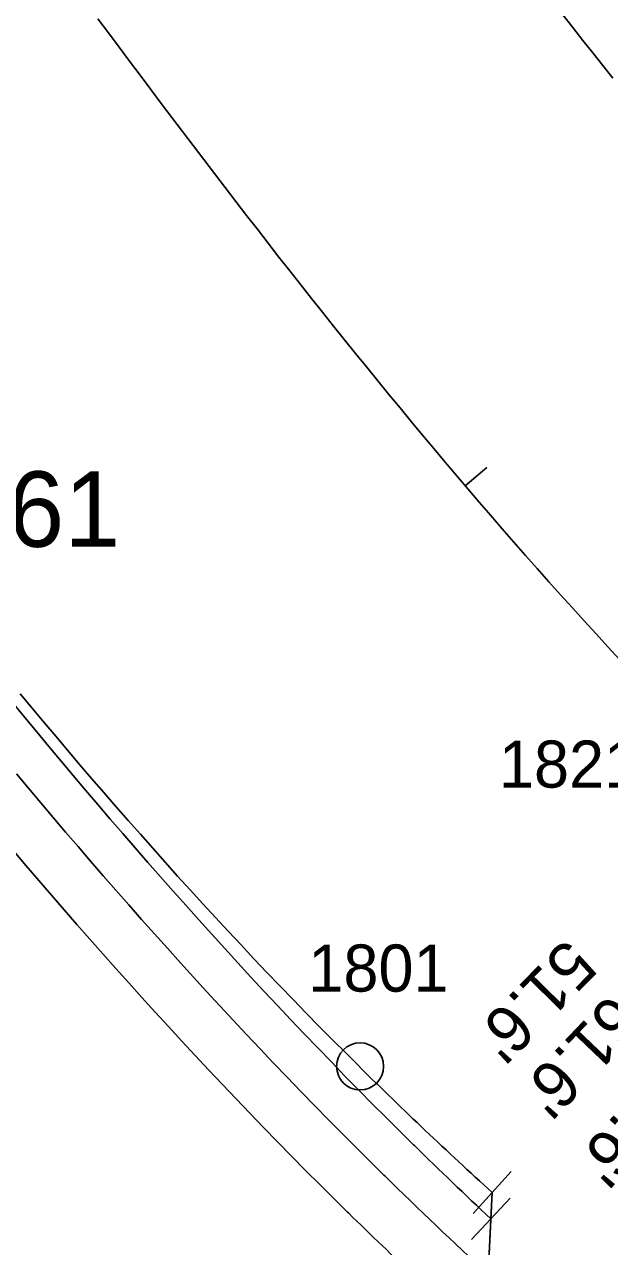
# Model space of a CAD drawing. Extents: x 7581380 to 7602708, y 543740 to 556109.
# Drawn here: x 7591884.2 to 7591946.3, y 549762.1 to 549891.7 of the extents above; entities that cross this region are included whole.
import ezdxf

# ---------------------------------------------------------------- set-up
doc = ezdxf.new("R2010")
doc.units = 0
for name, color, linetype in [('E_SURV_BNDRY_AccessControl', 7, 'Continuous'), ('E_SURV_BNDRY_ROW', 7, 'Continuous'), ('E_SURV_MON_FdMon', 7, 'Continuous'), ('E_SURV_MON_FdMonTx', 7, 'Continuous'), ('P_RW_ALIGN_Prim', 7, 'Continuous'), ('P_RW_ALIGN_PrimTic', 7, 'Continuous'), ('P_RW_EASE_Perm', 7, 'Continuous'), ('P_RW_EASE_PermTx', 7, 'Continuous'), ('P_RW_FEE_Access', 7, 'Continuous'), ('P_RW_FEE_AccessTx', 7, 'Continuous'), ('P_RW_FILE_AreaShapeEasePerm', 7, 'Continuous'), ('P_RW_FILE_AreaShapeFee', 7, 'Continuous'), ('P_RW_FILE_AreaShapeRemain', 7, 'Continuous'), ('P_RW_FILE_NumTx', 7, 'Continuous')]:
    doc.layers.add(name, color=color, linetype=linetype)

msp = doc.modelspace()

# ---------------------------------------------------------------- linework, layer by layer
at = {"layer": 'E_SURV_BNDRY_AccessControl'}
msp.add_line((7591935.84, 549770.05), (7591931.8, 549765.61), dxfattribs=at)
msp.add_lwpolyline([(7591883.76, 549820.72), (7591885, 549819.22), (7591886.25, 549817.72), (7591887.51, 549816.23), (7591888.78, 549814.73), (7591890.05, 549813.24), (7591891.32, 549811.75), (7591892.61, 549810.27), (7591893.9, 549808.78), (7591895.2, 549807.3), (7591896.5, 549805.82), (7591897.81, 549804.34), (7591899.13, 549802.86), (7591900.45, 549801.39), (7591901.78, 549799.92), (7591903.12, 549798.46), (7591904.47, 549796.99), (7591905.82, 549795.53), (7591907.18, 549794.08), (7591908.55, 549792.62), (7591909.93, 549791.17), (7591911.31, 549789.73), (7591912.7, 549788.29), (7591914.1, 549786.85), (7591915.51, 549785.41), (7591916.92, 549783.98), (7591918.35, 549782.56), (7591919.71, 549781.21)], dxfattribs=at)
msp.add_lwpolyline([(7591883.76, 549820.72), (7591885, 549819.22), (7591886.25, 549817.72), (7591887.51, 549816.23), (7591888.78, 549814.73), (7591890.05, 549813.24), (7591891.32, 549811.75), (7591892.61, 549810.27), (7591893.9, 549808.78), (7591895.2, 549807.3), (7591896.5, 549805.82), (7591897.81, 549804.34), (7591899.13, 549802.86), (7591900.45, 549801.39), (7591901.78, 549799.92), (7591903.12, 549798.46), (7591904.47, 549796.99), (7591905.82, 549795.53), (7591907.18, 549794.08), (7591908.55, 549792.62), (7591909.93, 549791.17), (7591911.31, 549789.73), (7591912.7, 549788.29), (7591914.1, 549786.85), (7591915.51, 549785.41), (7591916.92, 549783.98), (7591918.35, 549782.56), (7591919.71, 549781.21)], dxfattribs=at)
msp.add_arc((7592239.19, 550104.13), 454.26, 225.3195, 227.7603, dxfattribs=at)
msp.add_arc((7592239.19, 550104.13), 454.26, 225.3195, 227.7603, dxfattribs=at)
at = {"layer": 'E_SURV_BNDRY_ROW'}
msp.add_line((7591933.82, 549767.83), (7591929.27, 549671.63), dxfattribs=at)
msp.add_lwpolyline([(7591939.82, 549894.65), (7591940.25, 549894.1), (7591941.31, 549892.75), (7591942.37, 549891.4), (7591943.43, 549890.05), (7591944.49, 549888.71), (7591945.56, 549887.37), (7591946.62, 549886.04)], dxfattribs=at)
at = {"layer": 'E_SURV_MON_FdMon'}
msp.add_circle((7591919.81, 549781.2), 2.5, dxfattribs=at)
at = {"layer": 'P_RW_ALIGN_Prim'}
msp.add_lwpolyline([(7591892, 549892.33), (7591893.12, 549890.83), (7591894.23, 549889.33), (7591895.35, 549887.84), (7591896.47, 549886.34), (7591897.59, 549884.85), (7591898.71, 549883.36), (7591899.83, 549881.87), (7591900.96, 549880.38), (7591902.09, 549878.89), (7591903.22, 549877.41), (7591904.35, 549875.92), (7591905.49, 549874.44), (7591906.62, 549872.96), (7591907.76, 549871.48), (7591908.91, 549870.01), (7591910.05, 549868.54), (7591911.2, 549867.06), (7591912.35, 549865.6), (7591913.51, 549864.13), (7591914.67, 549862.66), (7591915.83, 549861.2), (7591916.99, 549859.74), (7591918.16, 549858.29), (7591919.33, 549856.83), (7591920.51, 549855.38), (7591921.68, 549853.94), (7591922.87, 549852.49), (7591924.05, 549851.05), (7591925.24, 549849.61), (7591926.43, 549848.17), (7591927.63, 549846.74), (7591928.83, 549845.31), (7591930.04, 549843.89), (7591931.25, 549842.47), (7591932.46, 549841.05), (7591933.68, 549839.63), (7591934.9, 549838.22), (7591936.13, 549836.82), (7591937.36, 549835.41), (7591938.6, 549834.01), (7591939.84, 549832.62), (7591941.08, 549831.23), (7591942.33, 549829.84), (7591943.59, 549828.46), (7591944.85, 549827.08), (7591946.11, 549825.71), (7591947.38, 549824.34)], dxfattribs=at)
at = {"layer": 'P_RW_ALIGN_PrimTic'}
msp.add_lwpolyline([(7591933.25, 549844.75), (7591930.96, 549842.8)], dxfattribs=at)
at = {"layer": 'P_RW_EASE_Perm'}
msp.add_lwpolyline([(7591883.06, 549804.04), (7591884.39, 549802.48), (7591885.72, 549800.92), (7591887.06, 549799.37), (7591888.41, 549797.81), (7591889.77, 549796.25), (7591891.13, 549794.7), (7591892.5, 549793.15), (7591893.88, 549791.6), (7591895.27, 549790.05), (7591896.66, 549788.5), (7591898.06, 549786.96), (7591899.47, 549785.42), (7591900.89, 549783.88), (7591902.32, 549782.35), (7591903.75, 549780.81), (7591905.2, 549779.28), (7591906.65, 549777.75), (7591908.11, 549776.23), (7591909.57, 549774.71), (7591911.05, 549773.19), (7591912.54, 549771.68), (7591914.03, 549770.17), (7591915.53, 549768.66), (7591917.05, 549767.16), (7591918.47, 549765.75)], dxfattribs=at)
msp.add_arc((7592258.91, 550112.61), 486.01, 225.5514, 227.8999, dxfattribs=at)
at = {"layer": 'P_RW_FEE_Access'}
msp.add_line((7591935.74, 549767.21), (7591931.64, 549762.83), dxfattribs=at)
msp.add_lwpolyline([(7591882.97, 549819.77), (7591884.24, 549818.22), (7591885.51, 549816.68), (7591886.8, 549815.14), (7591888.09, 549813.59), (7591889.38, 549812.05), (7591890.68, 549810.51), (7591891.99, 549808.97), (7591893.31, 549807.44), (7591894.63, 549805.9), (7591895.96, 549804.37), (7591897.29, 549802.84), (7591898.64, 549801.31), (7591899.99, 549799.78), (7591901.34, 549798.26), (7591902.71, 549796.74), (7591904.08, 549795.22), (7591905.45, 549793.7), (7591906.84, 549792.18), (7591908.23, 549790.67), (7591909.63, 549789.16), (7591911.04, 549787.66), (7591912.46, 549786.15), (7591913.88, 549784.66), (7591915.32, 549783.16), (7591916.76, 549781.67), (7591918.2, 549780.18), (7591919.66, 549778.69), (7591921.13, 549777.21), (7591922.6, 549775.74), (7591924.08, 549774.26), (7591925.49, 549772.88)], dxfattribs=at)
msp.add_arc((7592258.91, 550112.61), 476.01, 225.5514, 226.9045, dxfattribs=at)
at = {"layer": 'P_RW_FILE_AreaShapeEasePerm'}
for p, q in [((7591925.49, 549772.88), (7591925.57, 549772.8)), ((7591918.57, 549765.66), (7591918.47, 549765.75)), ((7591933.69, 549765.02), (7591933.07, 549752))]:
    msp.add_line(p, q, dxfattribs=at)
for points in [[(7591882.97, 549819.77), (7591884.24, 549818.22), (7591885.51, 549816.68), (7591886.8, 549815.14), (7591888.09, 549813.59), (7591889.38, 549812.05), (7591890.68, 549810.51), (7591891.99, 549808.97), (7591893.31, 549807.44), (7591894.63, 549805.9), (7591895.96, 549804.37), (7591897.29, 549802.84), (7591898.64, 549801.31), (7591899.99, 549799.78), (7591901.34, 549798.26), (7591902.71, 549796.74), (7591904.08, 549795.22), (7591905.45, 549793.7), (7591906.84, 549792.18), (7591908.23, 549790.67), (7591909.63, 549789.16), (7591911.04, 549787.66), (7591912.46, 549786.15), (7591913.88, 549784.66), (7591915.32, 549783.16), (7591916.76, 549781.67), (7591918.2, 549780.18), (7591919.66, 549778.69), (7591921.13, 549777.21), (7591922.6, 549775.74), (7591924.08, 549774.26), (7591925.49, 549772.88)], [(7591918.47, 549765.75), (7591917.05, 549767.16), (7591915.53, 549768.66), (7591914.03, 549770.17), (7591912.54, 549771.68), (7591911.05, 549773.19), (7591909.57, 549774.71), (7591908.11, 549776.23), (7591906.65, 549777.75), (7591905.2, 549779.28), (7591903.75, 549780.81), (7591902.32, 549782.35), (7591900.89, 549783.88), (7591899.47, 549785.42), (7591898.06, 549786.96), (7591896.66, 549788.5), (7591895.27, 549790.05), (7591893.88, 549791.6), (7591892.5, 549793.15), (7591891.13, 549794.7), (7591889.77, 549796.25), (7591888.41, 549797.81), (7591887.06, 549799.37), (7591885.72, 549800.92), (7591884.39, 549802.48), (7591883.06, 549804.04)]]:
    msp.add_lwpolyline(points, dxfattribs=at)
for radius, end in [(476.01, 226.9045), (486.01, 227.8999)]:
    msp.add_arc((7592258.91, 550112.61), radius, 225.5514, end, dxfattribs=at)
at = {"layer": 'P_RW_FILE_AreaShapeFee'}
for p, q in [((7591919.78, 549781.14), (7591919.71, 549781.21)), ((7591919.71, 549781.21), (7591919.78, 549781.14)), ((7591925.57, 549772.8), (7591925.49, 549772.88)), ((7591922.33, 549769.67), (7591922.42, 549769.58)), ((7591933.41, 549759.14), (7591933.82, 549767.83)), ((7591933.82, 549767.83), (7591933.69, 549765.02))]:
    msp.add_line(p, q, dxfattribs=at)
for points in [[(7591925.49, 549772.88), (7591924.08, 549774.26), (7591922.6, 549775.74), (7591921.13, 549777.21), (7591919.66, 549778.69), (7591918.2, 549780.18), (7591916.76, 549781.67), (7591915.32, 549783.16), (7591913.88, 549784.66), (7591912.46, 549786.15), (7591911.04, 549787.66), (7591909.63, 549789.16), (7591908.23, 549790.67), (7591906.84, 549792.18), (7591905.45, 549793.7), (7591904.08, 549795.22), (7591902.71, 549796.74), (7591901.34, 549798.26), (7591899.99, 549799.78), (7591898.64, 549801.31), (7591897.29, 549802.84), (7591895.96, 549804.37), (7591894.63, 549805.9), (7591893.31, 549807.44), (7591891.99, 549808.97), (7591890.68, 549810.51), (7591889.38, 549812.05), (7591888.09, 549813.59), (7591886.8, 549815.14), (7591885.51, 549816.68), (7591884.24, 549818.22), (7591882.97, 549819.77)], [(7591919.71, 549781.21), (7591918.35, 549782.56), (7591916.92, 549783.98), (7591915.51, 549785.41), (7591914.1, 549786.85), (7591912.7, 549788.29), (7591911.31, 549789.73), (7591909.93, 549791.17), (7591908.55, 549792.62), (7591907.18, 549794.08), (7591905.82, 549795.53), (7591904.47, 549796.99), (7591903.12, 549798.46), (7591901.78, 549799.92), (7591900.45, 549801.39), (7591899.13, 549802.86), (7591897.81, 549804.34), (7591896.5, 549805.82), (7591895.2, 549807.3), (7591893.9, 549808.78), (7591892.61, 549810.27), (7591891.32, 549811.75), (7591890.05, 549813.24), (7591888.78, 549814.73), (7591887.51, 549816.23), (7591886.25, 549817.72), (7591885, 549819.22), (7591883.76, 549820.72)], [(7591883.76, 549820.72), (7591885, 549819.22), (7591886.25, 549817.72), (7591887.51, 549816.23), (7591888.78, 549814.73), (7591890.05, 549813.24), (7591891.32, 549811.75), (7591892.61, 549810.27), (7591893.9, 549808.78), (7591895.2, 549807.3), (7591896.5, 549805.82), (7591897.81, 549804.34), (7591899.13, 549802.86), (7591900.45, 549801.39), (7591901.78, 549799.92), (7591903.12, 549798.46), (7591904.47, 549796.99), (7591905.82, 549795.53), (7591907.18, 549794.08), (7591908.55, 549792.62), (7591909.93, 549791.17), (7591911.31, 549789.73), (7591912.7, 549788.29), (7591914.1, 549786.85), (7591915.51, 549785.41), (7591916.92, 549783.98), (7591918.35, 549782.56), (7591919.71, 549781.21)], [(7591883.34, 549812.25), (7591884.64, 549810.7), (7591885.94, 549809.15), (7591887.25, 549807.6), (7591888.57, 549806.05), (7591889.89, 549804.51), (7591891.22, 549802.96), (7591892.56, 549801.42), (7591893.91, 549799.88), (7591895.26, 549798.33), (7591896.62, 549796.8), (7591897.98, 549795.26), (7591899.36, 549793.73), (7591900.74, 549792.2), (7591902.13, 549790.67), (7591903.53, 549789.14), (7591904.93, 549787.62), (7591906.34, 549786.1), (7591907.76, 549784.58), (7591909.19, 549783.06), (7591910.63, 549781.55), (7591912.07, 549780.04), (7591913.52, 549778.54), (7591914.99, 549777.03), (7591916.45, 549775.54), (7591917.93, 549774.04), (7591919.42, 549772.55), (7591920.92, 549771.07), (7591922.33, 549769.67)]]:
    msp.add_lwpolyline(points, dxfattribs=at)
for centre, radius, start, end in [((7592239.19, 550104.13), 454.26, 225.3195, 227.7603), ((7592239.19, 550104.13), 454.26, 225.3195, 227.7603), ((7592258.91, 550112.61), 476.01, 225.5514, 226.9045), ((7592258.91, 550112.61), 480.51, 225.5514, 227.3593)]:
    msp.add_arc(centre, radius, start, end, dxfattribs=at)
at = {"layer": 'P_RW_FILE_AreaShapeRemain'}
for p, q in [((7591925.49, 549772.88), (7591925.57, 549772.8)), ((7591925.57, 549772.8), (7591925.49, 549772.88))]:
    msp.add_line(p, q, dxfattribs=at)
for points in [[(7591792.99, 549939.34), (7591475.51, 549956.39), (7591465.97, 549716.25), (7591456.86, 549487.26), (7591773.7, 549469.66), (7591783.29, 549699.41), (7591930.21, 549691.61), (7591933.69, 549765.02)], [(7591939.82, 549894.65), (7591940.25, 549894.1), (7591941.31, 549892.75), (7591942.37, 549891.4), (7591943.43, 549890.05), (7591944.49, 549888.71), (7591945.56, 549887.37), (7591946.62, 549886.04)], [(7591882.97, 549819.77), (7591884.24, 549818.22), (7591885.51, 549816.68), (7591886.8, 549815.14), (7591888.09, 549813.59), (7591889.38, 549812.05), (7591890.68, 549810.51), (7591891.99, 549808.97), (7591893.31, 549807.44), (7591894.63, 549805.9), (7591895.96, 549804.37), (7591897.29, 549802.84), (7591898.64, 549801.31), (7591899.99, 549799.78), (7591901.34, 549798.26), (7591902.71, 549796.74), (7591904.08, 549795.22), (7591905.45, 549793.7), (7591906.84, 549792.18), (7591908.23, 549790.67), (7591909.63, 549789.16), (7591911.04, 549787.66), (7591912.46, 549786.15), (7591913.88, 549784.66), (7591915.32, 549783.16), (7591916.76, 549781.67), (7591918.2, 549780.18), (7591919.66, 549778.69), (7591921.13, 549777.21), (7591922.6, 549775.74), (7591924.08, 549774.26), (7591925.49, 549772.88)], [(7591925.49, 549772.88), (7591924.08, 549774.26), (7591922.6, 549775.74), (7591921.13, 549777.21), (7591919.66, 549778.69), (7591918.2, 549780.18), (7591916.76, 549781.67), (7591915.32, 549783.16), (7591913.88, 549784.66), (7591912.46, 549786.15), (7591911.04, 549787.66), (7591909.63, 549789.16), (7591908.23, 549790.67), (7591906.84, 549792.18), (7591905.45, 549793.7), (7591904.08, 549795.22), (7591902.71, 549796.74), (7591901.34, 549798.26), (7591899.99, 549799.78), (7591898.64, 549801.31), (7591897.29, 549802.84), (7591895.96, 549804.37), (7591894.63, 549805.9), (7591893.31, 549807.44), (7591891.99, 549808.97), (7591890.68, 549810.51), (7591889.38, 549812.05), (7591888.09, 549813.59), (7591886.8, 549815.14), (7591885.51, 549816.68), (7591884.24, 549818.22), (7591882.97, 549819.77)]]:
    msp.add_lwpolyline(points, dxfattribs=at)
msp.add_arc((7592258.91, 550112.61), 476.01, 225.5514, 226.9045, dxfattribs=at)
msp.add_arc((7592258.91, 550112.61), 476.01, 225.5514, 226.9045, dxfattribs=at)

# ---------------------------------------------------------------- texts
at = {"layer": 'E_SURV_MON_FdMonTx'}
for s, p in [('1821', (7591934.54, 549810.77)), ('1801', (7591914.32, 549789.13))]:
    msp.add_text(s, height=5, dxfattribs=at).set_placement(p)
at = {"layer": 'P_RW_EASE_PermTx'}
for rotation, p in [(226.329, (7591946.46, 549789.14)), (227.8999, (7591952.1, 549781.97))]:
    msp.add_text("61.6'", height=5, rotation=rotation, dxfattribs=at).set_placement(p)
at = {"layer": 'P_RW_FEE_AccessTx'}
msp.add_text("51.6'", height=5, rotation=225.5514, dxfattribs=at).set_placement((7591941.7, 549794.94))
at = {"layer": 'P_RW_FILE_NumTx'}
msp.add_text('061', height=8, dxfattribs=at).set_placement((7591876.52, 549836.32))

doc.saveas('drawing.dxf')
